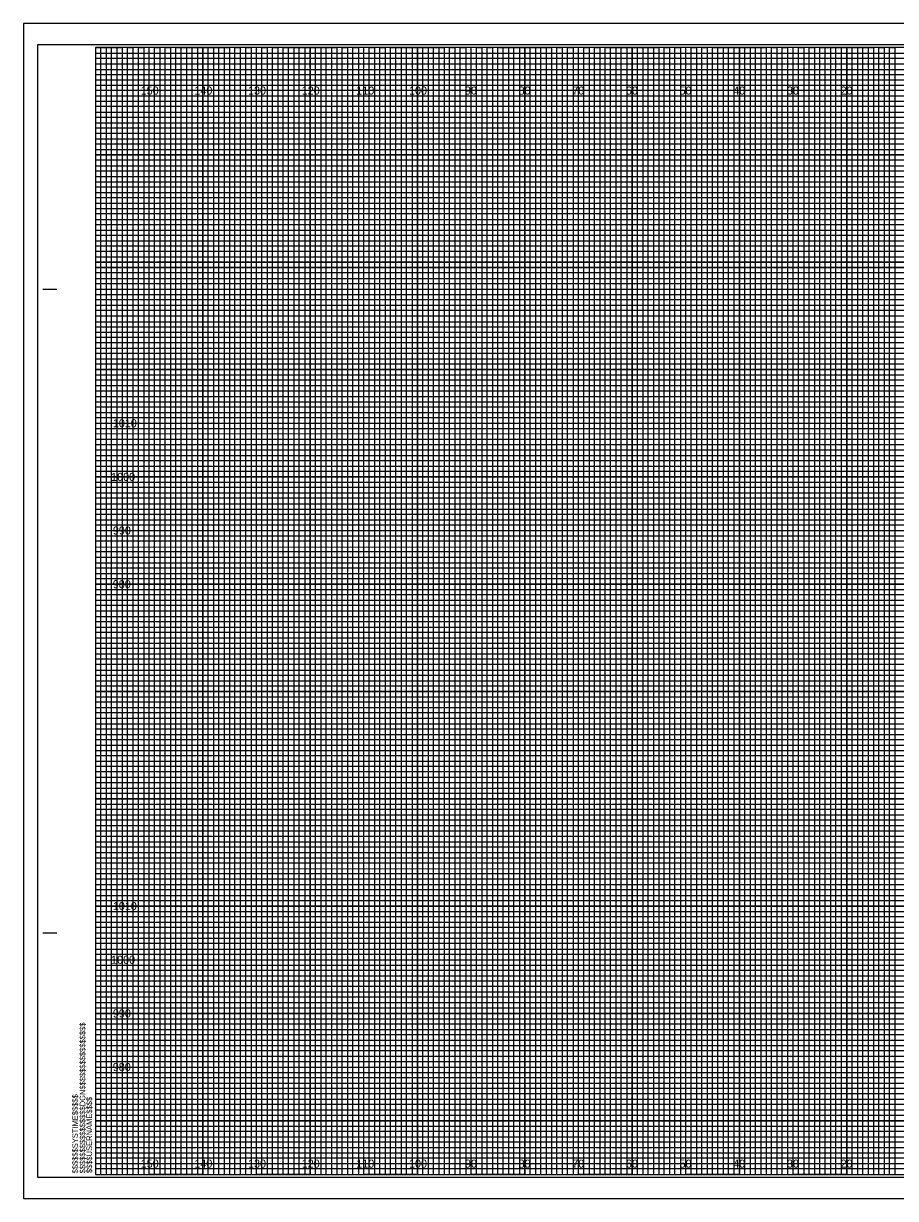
# Model space of a CAD drawing. Extents: x -13 to 323, y -5 to 215.
# Drawn here: x -13.4 to 149.1, y -4.5 to 214.5 of the extents above; entities that cross this region are included whole.
import ezdxf

# ---------------------------------------------------------------- set-up
doc = ezdxf.new("R2010")
doc.units = 0
for name, color, linetype in [('Exist Cross Section Cell', 7, 'Continuous'), ('Exist XS Center Line Elevation Label', 7, 'Continuous'), ('Exist XS Ground Line', 7, 'Continuous'), ('Prop XS Dump Level', 7, 'Continuous'), ('Prop XS Finish Grade', 7, 'Continuous'), ('Prop XS Finish Grade Earthwork', 7, 'Continuous'), ('Prop XS Hydro Elevations', 7, 'Continuous'), ('Prop XS Pvmt Edge Slope', 7, 'Continuous'), ('Prop XS SS Elevation Text', 7, 'Continuous'), ('Prop XS Subgrade CurbGutter', 7, 'Continuous'), ('Prop XS Subgrade Earthwork', 7, 'Continuous')]:
    doc.layers.add(name, color=color, linetype=linetype)

msp = doc.modelspace()

# ---------------------------------------------------------------- linework, layer by layer
at = {"layer": 'Exist XS Center Line Elevation Label'}
for points in [[(0, 210), (5, 210), (5, 0), (15, 0), (15, 210), (25, 210), (25, 0), (35, 0), (35, 210), (45, 210), (45, 0), (55, 0), (55, 210), (65, 210), (65, 0), (75, 0), (75, 210), (85, 210), (85, 0), (95, 0), (95, 210), (105, 210), (105, 0), (115, 0), (115, 210), (125, 210), (125, 0), (135, 0), (135, 210), (145, 210), (145, 0), (155, 0)], [(0, 205), (275, 205)], [(0, 185), (320, 185), (320, 195), (0, 195)], [(0, 165), (320, 165), (320, 175), (0, 175)], [(0, 145), (320, 145), (320, 155), (0, 155)], [(0, 125), (320, 125), (320, 135), (0, 135)], [(0, 105), (320, 105), (320, 115), (0, 115)], [(0, 85), (320, 85), (320, 95), (0, 95)], [(0, 65), (320, 65), (320, 75), (0, 75)], [(0, 45), (320, 45), (320, 55), (0, 55)], [(0, 25), (320, 25), (320, 35), (0, 35)], [(0, 5), (320, 5), (320, 15), (0, 15)]]:
    msp.add_lwpolyline(points, dxfattribs=at)
at = {"layer": 'Exist XS Ground Line'}
for p, q in [((10, 210), (0, 210)), ((10, 0), (10, 210)), ((30, 210), (20, 210)), ((20, 210), (20, 0)), ((30, 0), (30, 210)), ((50, 210), (40, 210)), ((40, 210), (40, 0)), ((50, 0), (50, 210)), ((70, 210), (60, 210)), ((60, 210), (60, 0)), ((70, 0), (70, 210)), ((90, 210), (80, 210)), ((80, 210), (80, 0)), ((90, 0), (90, 210)), ((110, 210), (100, 210)), ((100, 210), (100, 0)), ((110, 0), (110, 210)), ((130, 210), (120, 210)), ((120, 210), (120, 0)), ((130, 0), (130, 210)), ((150, 210), (140, 210)), ((140, 210), (140, 0)), ((20, 0), (10, 0)), ((40, 0), (30, 0)), ((60, 0), (50, 0)), ((80, 0), (70, 0)), ((100, 0), (90, 0)), ((120, 0), (110, 0)), ((140, 0), (130, 0))]:
    msp.add_line(p, q, dxfattribs=at)
for points in [[(0, 200), (320, 200), (320, 190), (0, 190)], [(0, 180), (320, 180), (320, 170), (0, 170)], [(0, 160), (320, 160), (320, 150), (0, 150)], [(0, 140), (320, 140), (320, 130), (0, 130)], [(0, 120), (320, 120), (320, 110), (0, 110)], [(0, 100), (320, 100), (320, 90), (0, 90)], [(0, 80), (320, 80), (320, 70), (0, 70)], [(0, 60), (320, 60), (320, 50), (0, 50)], [(0, 40), (320, 40), (320, 30), (0, 30)], [(0, 20), (320, 20), (320, 10), (0, 10)]]:
    msp.add_lwpolyline(points, dxfattribs=at)
at = {"layer": 'Prop XS Dump Level'}
for p, q in [((0, 209), (260, 209)), ((260, 207.98), (0, 207.98)), ((0, 207.98), (0, 207)), ((0, 207), (260, 207)), ((260, 205.89), (0, 205.89)), ((0, 205.89), (0, 204)), ((0, 204), (320, 204))]:
    msp.add_line(p, q, dxfattribs=at)
for points in [[(0, 203), (270, 203), (320, 203), (320, 202), (0, 202)], [(0, 201), (320, 201), (320, 199), (0, 199)], [(0, 198), (320, 198), (320, 197), (0, 196.98)], [(0, 196), (320, 196), (320, 194), (0, 194)], [(0, 193), (320, 193), (320, 192), (0, 192)], [(0, 191), (320, 191), (320, 189), (0, 189)], [(0, 188), (320, 188), (320, 187), (0, 187)], [(0, 186), (320, 186), (320, 184), (0, 184)], [(0, 183), (320, 183), (320, 182), (0, 182)], [(0, 181), (320, 181), (320, 179), (0, 179)], [(0, 178), (320, 178), (320, 177), (0, 177)], [(0, 176), (320, 176), (320, 173.95), (320, 173), (320, 172), (0, 172)], [(0, 174), (320, 174), (320, 173), (0, 173)], [(0, 171), (320, 171), (320, 169), (0, 169.03)], [(0, 169.03), (320, 169), (320, 168), (0, 168)], [(0, 167), (320, 167), (320, 166), (0, 166)], [(0, 164), (320, 164), (320, 163), (0, 163)], [(0, 162), (320, 162), (320, 161), (0, 161)], [(-0.07, 158.89), (320, 158.89), (320, 157.88), (-0.07, 157.88)], [(0, 157), (320, 157), (320, 156), (0, 156)], [(0, 154), (320, 154), (320, 153), (0, 153)], [(0, 152), (320, 152), (320, 151), (0, 151)], [(0, 149), (320, 149), (320, 148), (0, 148)], [(0, 147), (320, 147), (320, 146), (0, 146)], [(0, 144), (320, 144), (320, 143), (0, 143)], [(0, 142), (320, 142), (320, 141), (0, 141)], [(0, 139), (320, 139), (319.99, 137.98), (0, 138)], [(0, 137), (320, 137), (320, 136), (0, 136)], [(0, 134), (320, 134), (320, 133), (0, 133)], [(0, 132), (320, 132), (320, 131), (0, 131)], [(0, 129), (320, 129), (320, 128), (0, 128)], [(0, 127), (320, 127), (320, 126), (0, 126)], [(0, 124), (320, 124), (320, 123), (0, 123)], [(0, 122), (320, 122), (320, 121), (0, 121)], [(0, 119), (320, 119), (320, 118), (0, 118)], [(0, 116.99), (320.07, 116.91), (320, 116), (0, 116)], [(0, 114), (320, 114), (320, 113), (0, 113)], [(0, 112), (320, 112), (320, 111), (0, 111)], [(0, 109), (320, 109), (320, 108), (0, 108)], [(0, 107), (320, 107), (320, 106), (0, 106)], [(0, 104), (320, 104), (320, 103), (0, 103)], [(0, 102), (320, 102), (320, 101), (0, 101)], [(0, 99), (320, 99), (320, 98), (0, 98)], [(0, 97), (320, 97), (320, 96), (0, 96)], [(0, 94), (320, 94), (320, 93), (0, 93)], [(0, 92), (320, 92), (320, 91), (0, 91)], [(0, 89), (320, 89), (320, 88), (0, 88)], [(0, 87), (320, 87), (320, 86), (0, 86)], [(0, 84), (320, 84), (320, 83), (0, 83)], [(0, 82), (320, 82), (320, 81), (0, 81)], [(0, 79), (320, 79), (319.99, 77.98), (0, 78)], [(0, 77), (320, 77), (320, 76), (0, 76)], [(0, 74), (320, 74), (320, 73), (0, 73)], [(0, 72), (320, 72), (320, 71), (0, 71)], [(0, 69), (320, 69), (320, 68), (0, 68)], [(0, 67), (320, 67), (320, 66), (0, 66)], [(0, 64), (320, 64), (320, 63), (0, 63)], [(0, 62), (320, 62), (320, 61), (0, 61)], [(0, 59), (320, 59), (320, 58), (0, 58)], [(0, 56.99), (320.07, 56.91), (320, 56), (0, 56)], [(0, 54), (320, 54), (320, 53), (0, 53)], [(0, 52), (320, 52), (320, 51), (0, 51)], [(0, 49), (320, 49), (320, 48), (0, 48)], [(0, 47), (320, 47), (320, 46), (0, 46)], [(0, 44), (320, 44), (320, 43), (0, 43)], [(0, 42), (320, 42), (320, 41), (0, 41)], [(0, 39), (320, 39), (320, 38), (0, 38)], [(0, 37), (320, 37), (320, 36), (0, 36)], [(0, 34), (320, 34), (320, 33), (0, 33)], [(0, 32), (320, 32), (320, 31), (0, 31)], [(0, 29), (320, 29), (320, 28), (0, 28)], [(0, 27), (320, 27), (320, 26), (0, 26)], [(0, 24), (320, 24), (320, 23), (0, 23)], [(0, 22), (320, 22), (320, 21), (0, 21)], [(0, 19), (320, 19), (320, 18), (0, 18)], [(0, 17), (320, 17), (320, 16), (0, 16)], [(0, 14), (320, 14), (320, 13), (0, 13)], [(0, 12), (320, 12), (320, 11), (0, 11)], [(0, 9), (320, 9), (320, 8), (0, 8)], [(0, 7), (320, 7), (320, 6), (0, 6)], [(0, 4), (320, 4), (320, 3), (0, 3)], [(0, 2), (320, 2), (320, 1), (0, 1)]]:
    msp.add_lwpolyline(points, dxfattribs=at)
at = {"layer": 'Prop XS Finish Grade'}
for p, q in [((10, 0), (10, 210)), ((20, 0), (20, 210)), ((30, 0), (30, 210)), ((40, 0), (40, 210)), ((50, 0), (50, 210)), ((60, 0), (60, 210)), ((70, 0), (70, 210)), ((80, 0), (80, 210)), ((90, 0), (90, 210)), ((100, 0), (100, 210)), ((110, 0), (110, 210)), ((120, 0), (120, 210)), ((130, 0), (130, 210)), ((140, 0), (140, 210)), ((0, 200), (320, 200)), ((0, 190), (320, 190)), ((0, 180), (320, 180)), ((0, 170), (320, 170)), ((0, 160), (320, 160)), ((0, 150), (320, 150)), ((0, 140), (320, 140)), ((0, 130), (320, 130)), ((0, 120), (320, 120)), ((0, 110), (320, 110)), ((0, 100), (320, 100)), ((0, 90), (320, 90)), ((0, 80), (320, 80)), ((0, 70), (320, 70)), ((0, 60), (320, 60)), ((0, 50), (320, 50)), ((0, 40), (320, 40)), ((0, 30), (320, 30)), ((0, 20), (320, 20)), ((0, 10), (320, 10))]:
    msp.add_line(p, q, dxfattribs=at)
at = {"layer": 'Prop XS Finish Grade Earthwork'}
msp.add_lwpolyline([(-13.4, -4.5), (323.3, -4.5), (323.3, 214.5), (-13.4, 214.5)], close=True, dxfattribs=at)
at = {"layer": 'Prop XS Hydro Elevations'}
for p, q in [((-9.8, 165), (-7.3, 165)), ((-9.7, 165), (-7.2, 165)), ((-9.8, 45), (-7.3, 45)), ((-9.7, 45), (-7.2, 45))]:
    msp.add_line(p, q, dxfattribs=at)
msp.add_lwpolyline([(320, 210), (0, 210), (0, 0), (320, 0)], close=True, dxfattribs=at)
at = {"layer": 'Prop XS Pvmt Edge Slope'}
msp.add_lwpolyline([(-10.8, -0.5), (322.4, -0.5), (322.4, 210.5), (-10.8, 210.5)], close=True, dxfattribs=at)
at = {"layer": 'Prop XS SS Elevation Text'}
for points in [[(0, 0), (1, 0), (1, 210), (2, 210), (2, 0)], [(2, 0), (3, 0), (3, 210), (4, 210), (4, 0)], [(5, 0), (6, 0), (6, 210), (7, 210), (7, 0)], [(7, 0), (8, 0), (8, 210), (9, 210), (9, 0)], [(10, 0), (11, 0), (11, 210), (12, 210), (12, 0)], [(12, 0), (13, 0), (13, 210), (14, 210), (14, 0)], [(15, 0), (16, 0), (16, 210), (17, 210), (17, 0)], [(17, 0), (18, 0), (18, 210), (19, 210), (19, 0)], [(20, 0), (21, 0), (21, 210), (22, 210), (22, 0)], [(22, 0), (23, 0), (23, 210), (24, 210), (24, 0)], [(25, 0), (26, 0), (26, 210), (27, 210), (27, 0)], [(27, 0), (28, 0), (28, 210), (29, 210), (29, 0)], [(30, 0), (31, 0), (31, 210), (32, 210), (32, 0)], [(32, 0), (33, 0), (33, 210), (34, 210), (34, 0)], [(35, 0), (36, 0), (36, 210), (37, 210), (37, 0)], [(37, 0), (38, 0), (38, 210), (39, 210), (39, 0)], [(40, 0), (41, 0), (41, 210), (42, 210), (42, 0)], [(42, 0), (43, 0), (43, 210), (44, 210), (44, 0)], [(45, 0), (46, 0), (46, 210), (47, 210), (47, 0)], [(47, 0), (48, 0), (48, 210), (49, 210), (49, 0)], [(50, 0), (51, 0), (51, 210), (52, 210), (52, 0)], [(52, 0), (53, 0), (53, 210), (54, 210), (54, 0)], [(55, 0), (56, 0), (56, 210), (57, 210), (57, 0)], [(57, 0), (58, 0), (58, 210), (59, 210), (59, 0)], [(60, 0), (61, 0), (61, 210), (62, 210), (62, 0)], [(62, 0), (63, 0), (63, 210), (64, 210), (64, 0)], [(65, 0), (66, 0), (66, 210), (67, 210), (67, 0)], [(67, 0), (68, 0), (68, 210), (69, 210), (69, 0)], [(70, 0), (71, 0), (71, 210), (72, 210), (72, 0)], [(72, 0), (73, 0), (73, 210), (74, 210), (74, 0)], [(75, 0), (76, 0), (76, 210), (77, 210), (77, 0)], [(77, 0), (78, 0), (78, 210), (79, 210), (79, 0)], [(80, 0), (81, 0), (81, 210), (82, 210), (82, 0)], [(82, 0), (83, 0), (83, 210), (84, 210), (84, 0)], [(85, 0), (86, 0), (86, 210), (87, 210), (87, 0)], [(87, 0), (88, 0), (88, 210), (89, 210), (89, 0)], [(90, 0), (91, 0), (91, 210), (92, 210), (92, 0)], [(92, 0), (93, 0), (93, 210), (94, 210), (94, 0)], [(95, 0), (96, 0), (96, 210), (97, 210), (97, 0)], [(97, 0), (98, 0), (98, 210), (99, 210), (99, 0)], [(100, 0), (101, 0), (101, 210), (102, 210), (102, 0)], [(102, 0), (103, 0), (103, 210), (104, 210), (104, 0)], [(105, 0), (106, 0), (106, 210), (107, 210), (107, 0)], [(107, 0), (108, 0), (108, 210), (109, 210), (109, 0)], [(110, 0), (111, 0), (111, 210), (112, 210), (112, 0)], [(112, 0), (113, 0), (113, 210), (114, 210), (114, 0)], [(115, 0), (116, 0), (116, 210), (117, 210), (117, 0)], [(117, 0), (118, 0), (118, 210), (119, 210), (119, 0)], [(120, 0), (121, 0), (121, 210), (122, 210), (122, 0)], [(122, 0), (123, 0), (123, 210), (124, 210), (124, 0)], [(125, 0), (126, 0), (126, 210), (127, 210), (127, 0)], [(127, 0), (128, 0), (128, 210), (129, 210), (129, 0)], [(130, 0), (131, 0), (131, 210), (132, 210), (132, 0)], [(132, 0), (133, 0), (133, 210), (134, 210), (134, 0)], [(135, 0), (136, 0), (136, 210), (137, 210), (137, 0)], [(137, 0), (138, 0), (138, 210), (139, 210), (139, 0)], [(140, 0), (141, 0), (141, 210), (142, 210), (142, 0)], [(142, 0), (143, 0), (143, 210), (144, 210), (144, 0)], [(145, 0), (146, 0), (146, 210), (147, 210), (147, 0)], [(147, 0), (148, 0), (148, 210), (149, 210), (149, 0)]]:
    msp.add_lwpolyline(points, dxfattribs=at)
at = {"layer": 'Prop XS Subgrade Earthwork'}
for p, q in [((323.3, 214.5), (-13.4, 214.5)), ((-13.4, 214.5), (-13.4, -4.5)), ((-13.4, -4.5), (323.3, -4.5))]:
    msp.add_line(p, q, dxfattribs=at)

# ---------------------------------------------------------------- texts
at = {"layer": 'Exist Cross Section Cell'}
for s, p in [('150', (8.44, 201.25)), ('140', (18.44, 201.25)), ('130', (28.44, 201.25)), ('120', (38.44, 201.25)), ('110', (48.62, 201.25)), ('100', (58.44, 201.25)), ('90', (68.86, 201.25)), ('80', (78.86, 201.25)), ('70', (88.86, 201.25)), ('60', (98.86, 201.25)), ('50', (108.86, 201.25)), ('40', (118.86, 201.25)), ('30', (128.86, 201.25)), ('20', (138.86, 201.25)), ('150', (8.44, 1.25)), ('140', (18.44, 1.25)), ('130', (28.44, 1.25)), ('120', (38.44, 1.25)), ('110', (48.62, 1.25)), ('100', (58.44, 1.25)), ('90', (68.86, 1.25)), ('80', (78.86, 1.25)), ('70', (88.86, 1.25)), ('60', (98.86, 1.25)), ('50', (108.86, 1.25)), ('40', (118.86, 1.25)), ('30', (128.86, 1.25)), ('20', (138.86, 1.25))]:
    msp.add_text(s, height=1.5, dxfattribs=at).set_placement(p)
at = {"layer": 'Prop XS Hydro Elevations'}
for s, p in [('$$$$$$$$$$$$$$$$DGN$$$$$$$$$$$$$$$$', (-1.88, 0.18)), ('$$$$$$SYSTIME$$$$$', (-3.26, 0.18)), ('$$$$USERNAME$$$$', (-0.62, 0.23))]:
    msp.add_text(s, height=1.05, rotation=90, dxfattribs=at).set_placement(p)
at = {"layer": 'Prop XS Subgrade CurbGutter'}
for s, p in [('1010', (3.25, 139.25)), ('1000', (2.92, 129.25)), ('990', (3.26, 119.25)), ('980', (3.24, 109.25)), ('1010', (3.25, 49.25)), ('1000', (2.92, 39.25)), ('990', (3.26, 29.25)), ('980', (3.24, 19.25))]:
    msp.add_text(s, height=1.5, dxfattribs=at).set_placement(p)

doc.saveas('drawing.dxf')
